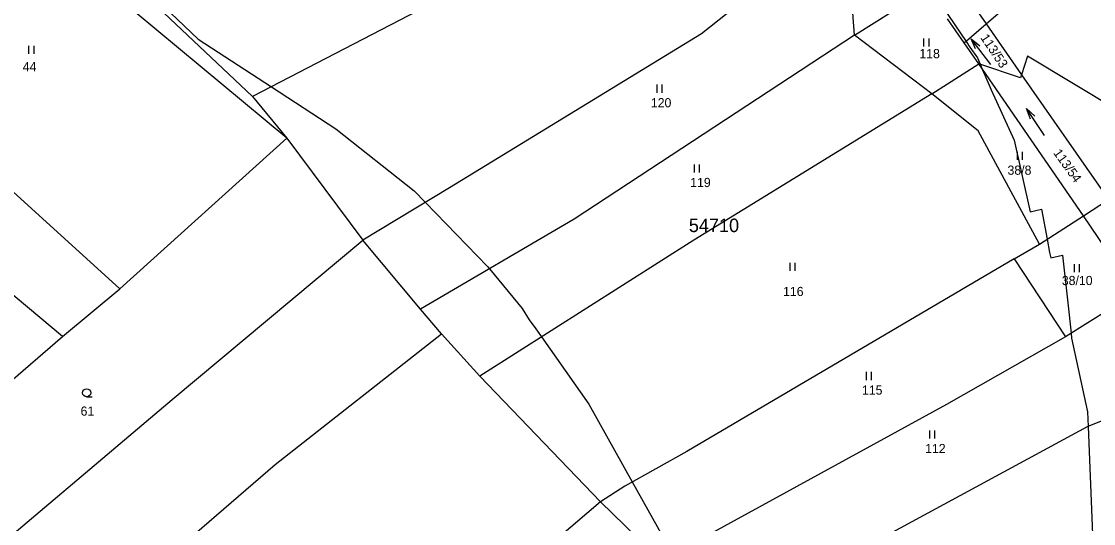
# Model space of a CAD drawing. Extents: x -749173 to -746119, y -1132678 to -1130338.
# Drawn here: x -747690.2 to -747491.9, y -1131098.8 to -1131005.9 of the extents above; entities that cross this region are included whole.
import ezdxf

# ---------------------------------------------------------------- set-up
doc = ezdxf.new("R2010")
doc.units = 0
for name, color, linetype in [('Vrstva 1', 7, 'Continuous'), ('Vrstva 18', 7, 'Continuous'), ('Vrstva 25', 7, 'Continuous'), ('Vrstva 52', 7, 'Continuous'), ('Vrstva 53', 7, 'Continuous'), ('Vrstva 6', 7, 'Continuous')]:
    doc.layers.add(name, color=color, linetype=linetype)

msp = doc.modelspace()

# ---------------------------------------------------------------- linework, layer by layer
at = {"layer": 'Vrstva 1'}
for points in [[(-747523.68, -1130989.16), (-747511.77, -1131006.31)], [(-747641.15, -1131027.46), (-747677.24, -1130997.39)], [(-747670.43, -1130998.05), (-747647.48, -1131019.78)], [(-747515.79, -1131009.83), (-747518.9, -1131005.41)], [(-747511.77, -1131006.31), (-747505.21, -1131015.73)], [(-747513.08, -1131013.69), (-747515.79, -1131009.83)], [(-747493.76, -1131041.86), (-747513.08, -1131013.69)], [(-747505.21, -1131015.73), (-747489.11, -1131038.86)], [(-747713.52, -1131017.65), (-747672.07, -1131055.39)], [(-747647.48, -1131019.78), (-747641.15, -1131027.46)], [(-747672.07, -1131055.39), (-747641.15, -1131027.46)], [(-747641.15, -1131027.46), (-747627.11, -1131046.39)], [(-747484.08, -1131056.18), (-747493.76, -1131041.86)], [(-747682.65, -1131064.18), (-747704.02, -1131046.27)], [(-747662.38, -1131075.87), (-747627.11, -1131046.39)], [(-747616.38, -1131059.15), (-747627.11, -1131046.39)], [(-747682.65, -1131064.18), (-747672.07, -1131055.39)], [(-747612.55, -1131063.71), (-747616.38, -1131059.15)], [(-747702.76, -1131081.57), (-747682.65, -1131064.18)], [(-747605.42, -1131071.52), (-747612.55, -1131063.71)], [(-747605.42, -1131071.52), (-747583.1, -1131094.79)], [(-747702.08, -1131109.45), (-747662.38, -1131075.87)], [(-747583.1, -1131094.79), (-747571.91, -1131105.73)]]:
    msp.add_lwpolyline(points, dxfattribs=at)
at = {"layer": 'Vrstva 25'}
for p, q in [((-747688.91, -1131010.36), (-747688.91, -1131011.86)), ((-747687.91, -1131011.86), (-747687.91, -1131010.36)), ((-747523.32, -1131009.02), (-747523.32, -1131010.52)), ((-747522.32, -1131010.52), (-747522.32, -1131009.02)), ((-747510.88, -1131013.83), (-747514.54, -1131009.07)), ((-747572.68, -1131017.56), (-747572.68, -1131019.06)), ((-747571.68, -1131019.06), (-747571.68, -1131017.56)), ((-747500.94, -1131027.01), (-747504.26, -1131022.01)), ((-747506.03, -1131029.99), (-747506.03, -1131031.49)), ((-747505.03, -1131031.49), (-747505.03, -1131029.99)), ((-747565.8, -1131032.33), (-747565.8, -1131033.83)), ((-747564.8, -1131033.83), (-747564.8, -1131032.33)), ((-747548.06, -1131050.56), (-747548.06, -1131052.06)), ((-747547.06, -1131052.06), (-747547.06, -1131050.56)), ((-747495.48, -1131050.79), (-747495.48, -1131052.29)), ((-747494.48, -1131052.29), (-747494.48, -1131050.79)), ((-747533.98, -1131070.77), (-747533.98, -1131072.27)), ((-747532.98, -1131072.27), (-747532.98, -1131070.77)), ((-747678.18, -1131075.37), (-747677.18, -1131075.37)), ((-747522.26, -1131081.59), (-747522.26, -1131083.09)), ((-747521.26, -1131083.09), (-747521.26, -1131081.59))]:
    msp.add_line(p, q, dxfattribs=at)
for points in [[(-747513.72, -1131010.96), (-747514.54, -1131009.07), (-747512.92, -1131010.35)], [(-747503.57, -1131023.96), (-747504.26, -1131022.01), (-747502.74, -1131023.4)]]:
    msp.add_lwpolyline(points, dxfattribs=at)
msp.add_circle((-747678.18, -1131074.62), 0.75, dxfattribs=at)
at = {"layer": 'Vrstva 52'}
for points in [[(-747680.5, -1130983.25), (-747669.34, -1130997.37), (-747667.75, -1130999.37), (-747657.56, -1131009.12), (-747643.99, -1131017.97), (-747632.06, -1131025.75), (-747617.56, -1131037.25), (-747615.5, -1131039.37), (-747604, -1131051.25), (-747603.65, -1131051.67), (-747597.62, -1131059), (-747596.31, -1131061.12), (-747595.1, -1131062.76), (-747594.19, -1131064), (-747594.01, -1131064.25), (-747585.25, -1131076.75), (-747577.22, -1131091.12), (-747569.73, -1131104.54)], [(-747519.75, -1131003.25), (-747515.47, -1131009.55), (-747514.75, -1131010.6), (-747513.37, -1131012.62), (-747512.88, -1131013.76), (-747512.61, -1131014.37), (-747510.81, -1131018.5), (-747506.56, -1131027.87)], [(-747506.56, -1131027.87), (-747503.62, -1131041.12), (-747501.5, -1131040.62), (-747500.46, -1131046.18), (-747500, -1131048.62), (-747499.81, -1131049.62), (-747497.62, -1131049.12), (-747496.65, -1131057.98), (-747496.04, -1131063.6), (-747495.94, -1131064.5), (-747493, -1131078.12), (-747492.89, -1131080.86), (-747491.46, -1131116.22)]]:
    msp.add_lwpolyline(points, dxfattribs=at)
at = {"layer": 'Vrstva 6'}
for points in [[(-747537.72, -1130986.92), (-747564.39, -1131008.14)], [(-747536.11, -1131008.38), (-747537.72, -1130986.92)], [(-747511.77, -1131006.31), (-747490.53, -1130988)], [(-747615.24, -1131003.06), (-747647.48, -1131019.78)], [(-747536.11, -1131008.38), (-747529.3, -1131004.16)], [(-747515.79, -1131009.83), (-747511.77, -1131006.31)], [(-747564.39, -1131008.14), (-747611.03, -1131036.67)], [(-747536.11, -1131008.38), (-747587.97, -1131042.46)], [(-747521.83, -1131019.25), (-747536.11, -1131008.38)], [(-747504.08, -1131012.3), (-747505.21, -1131015.73)], [(-747487.41, -1131022.36), (-747504.08, -1131012.3)], [(-747521.83, -1131019.25), (-747513.08, -1131013.69)], [(-747505.41, -1131016.33), (-747513.08, -1131013.69)], [(-747505.21, -1131015.73), (-747505.41, -1131016.33)], [(-747521.83, -1131019.25), (-747565.86, -1131046.34)], [(-747513.23, -1131026.12), (-747521.83, -1131019.25)], [(-747501.87, -1131047.09), (-747513.23, -1131026.12)], [(-747611.03, -1131036.67), (-747627.11, -1131046.39)], [(-747493.76, -1131041.86), (-747489.11, -1131038.86)], [(-747587.97, -1131042.46), (-747616.38, -1131059.15)], [(-747501.87, -1131047.09), (-747493.76, -1131041.86)], [(-747565.86, -1131046.34), (-747605.42, -1131071.52)], [(-747506.57, -1131049.83), (-747501.87, -1131047.09)], [(-747506.57, -1131049.83), (-747567.11, -1131085.51)], [(-747506.57, -1131049.83), (-747497.04, -1131064.23)], [(-747488.78, -1131059.1), (-747497.04, -1131064.23)], [(-747643.31, -1131087.92), (-747612.55, -1131063.71)], [(-747497.04, -1131064.23), (-747519.1, -1131076.81)], [(-747478.83, -1131075.18), (-747493.05, -1131080.92)], [(-747519.1, -1131076.81), (-747571.91, -1131105.73)], [(-747493.05, -1131080.92), (-747560.11, -1131117.26)], [(-747567.11, -1131085.51), (-747578.6, -1131091.89)], [(-747690.81, -1131128.96), (-747643.31, -1131087.92)], [(-747578.6, -1131091.89), (-747583.1, -1131094.79)], [(-747583.1, -1131094.79), (-747617.7, -1131124.35)]]:
    msp.add_lwpolyline(points, dxfattribs=at)

# ---------------------------------------------------------------- texts
at = {"layer": 'Vrstva 18'}
for s, rotation, p in [('113/53', 303.685, (-747512.88, -1131008.88)), ('113/54', 305.4633, (-747499.4, -1131030.21))]:
    msp.add_text(s, height=1.7, rotation=rotation, dxfattribs=at).set_placement(p)
for s, p in [('118', (-747524.11, -1131012.67)), ('44', (-747690, -1131015.09)), ('120', (-747573.79, -1131021.76)), ('38/8', (-747507.8, -1131034.25)), ('119', (-747566.51, -1131036.53)), ('38/10', (-747497.75, -1131054.68)), ('116', (-747549.33, -1131056.71)), ('115', (-747534.73, -1131074.97)), ('61', (-747679.3, -1131078.86)), ('112', (-747523.04, -1131085.79))]:
    msp.add_text(s, height=1.7, dxfattribs=at).set_placement(p)
at = {"layer": 'Vrstva 53'}
msp.add_text('54710', height=2.5, dxfattribs=at).set_placement((-747566.76, -1131044.87))

doc.saveas('drawing.dxf')
